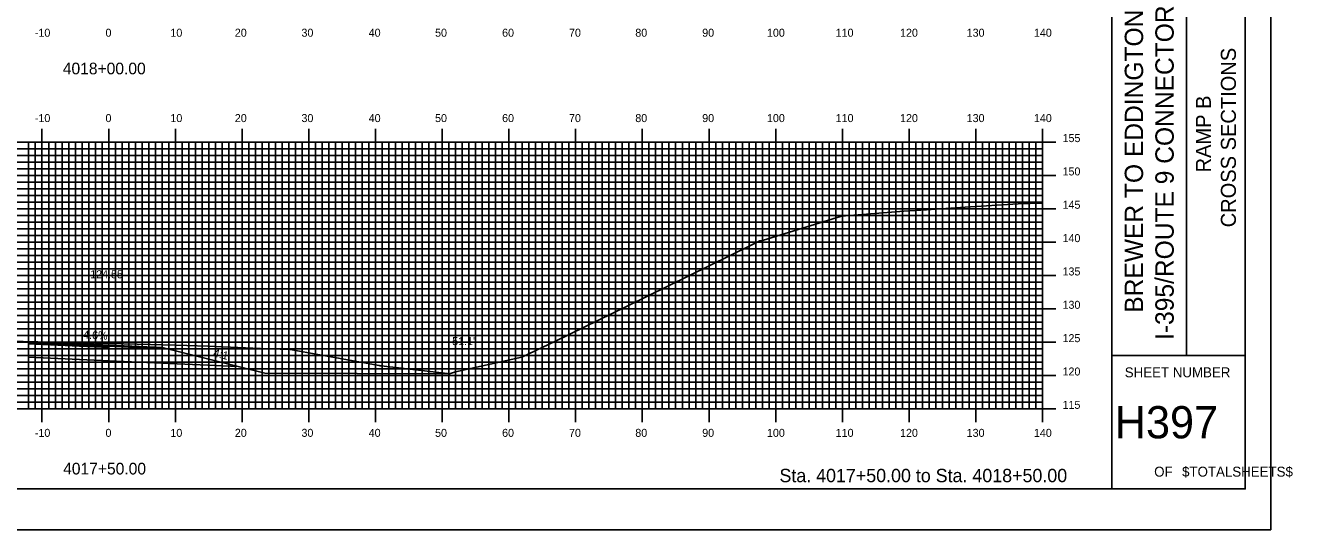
# Model space of a CAD drawing. Extents: x 854508 to 854851, y 364661 to 364881.
# Drawn here: x 854661.3 to 854851.3, y 364661.3 to 364736.9 of the extents above; entities that cross this region are included whole.
import ezdxf

# ---------------------------------------------------------------- set-up
doc = ezdxf.new("R2010")
doc.units = 0
for name, color, linetype in [('ANNOTATION', 7, 'Continuous'), ('BORDER', 7, 'Continuous'), ('D_Roadway_Centerline_Text', 7, 'Continuous'), ('D_Roadway_Edge_Shoulder', 7, 'Continuous'), ('D_Roadway_Edge_TW', 7, 'Continuous'), ('D_Roadway_Pavement', 7, 'Continuous'), ('D_Roadway_SubGrade', 7, 'Continuous'), ('D_Text_Standard', 7, 'Continuous'), ('H_V ANNOTATION', 7, 'Continuous'), ('M_Roadway_Centerline', 7, 'Continuous'), ('MAJOR', 7, 'Continuous'), ('MINOR', 7, 'Continuous'), ('PLOT BOUNDARY', 7, 'Continuous'), ('S_Roadway_Centerline', 7, 'Continuous')]:
    doc.layers.add(name, color=color, linetype=linetype)

msp = doc.modelspace()

# ---------------------------------------------------------------- linework, layer by layer
at = {"layer": 'ANNOTATION'}
msp.add_lwpolyline([(854693.24, 364685.7), (854697.24, 364684.7), (854724.92, 364684.64)], dxfattribs=at)
at = {"layer": 'BORDER'}
for p, q in [((854824.23, 364667.37), (854824.23, 364877.37)), ((854835.42, 364687.38), (854835.42, 364757.38)), ((854824.23, 364687.38), (854844.23, 364687.38))]:
    msp.add_line(p, q, dxfattribs=at)
msp.add_lwpolyline([(854524.23, 364667.37), (854844.23, 364667.37), (854844.23, 364877.37), (854524.23, 364877.37)], close=True, dxfattribs=at)
at = {"layer": 'D_Roadway_Edge_Shoulder'}
msp.add_lwpolyline([(854673.83, 364688.92), (854681.83, 364688.55), (854681.83, 364688.38), (854673.83, 364688.75)], close=True, dxfattribs=at)
at = {"layer": 'D_Roadway_Edge_TW'}
msp.add_lwpolyline([(854661.83, 364689.47), (854673.83, 364688.92), (854673.83, 364688.75), (854661.83, 364689.3)], close=True, dxfattribs=at)
at = {"layer": 'D_Roadway_Pavement'}
msp.add_lwpolyline([(854661.83, 364689.3), (854673.83, 364688.75), (854673.83, 364688.58), (854661.83, 364689.13)], close=True, dxfattribs=at)
for points in [[(854661.83, 364689.3), (854661.83, 364689.13)], [(854673.83, 364688.75), (854673.83, 364688.58)], [(854673.83, 364688.75), (854673.83, 364688.58)]]:
    msp.add_lwpolyline(points, dxfattribs=at)
at = {"layer": 'D_Roadway_SubGrade'}
msp.add_line((854661.83, 364694.43), (854661.83, 364687.13), dxfattribs=at)
for points in [[(854661.83, 364689.13), (854673.83, 364688.58), (854673.83, 364686.58), (854661.83, 364687.13)], [(854673.83, 364688.58), (854673.83, 364688.75), (854681.83, 364688.38), (854681.83, 364688.55), (854693.24, 364685.7), (854673.83, 364686.58)]]:
    msp.add_lwpolyline(points, close=True, dxfattribs=at)
at = {"layer": 'MAJOR'}
for p, q in [((854663.83, 364721.37), (854663.83, 364719.37)), ((854673.83, 364721.37), (854673.83, 364719.37)), ((854683.83, 364721.37), (854683.83, 364719.37)), ((854693.83, 364721.37), (854693.83, 364719.37)), ((854703.83, 364721.37), (854703.83, 364719.37)), ((854713.83, 364721.37), (854713.83, 364719.37)), ((854723.83, 364721.37), (854723.83, 364719.37)), ((854733.83, 364721.37), (854733.83, 364719.37)), ((854743.83, 364721.37), (854743.83, 364719.37)), ((854753.83, 364721.37), (854753.83, 364719.37)), ((854763.83, 364721.37), (854763.83, 364719.37)), ((854773.83, 364721.37), (854773.83, 364719.37)), ((854783.83, 364721.37), (854783.83, 364719.37)), ((854793.83, 364721.37), (854793.83, 364719.37)), ((854803.83, 364721.37), (854803.83, 364719.37)), ((854813.83, 364721.37), (854813.83, 364719.37)), ((854533.83, 364719.37), (854813.83, 364719.37)), ((854533.83, 364719.37), (854813.83, 364719.37)), ((854663.83, 364679.37), (854663.83, 364719.37)), ((854673.83, 364679.37), (854673.83, 364719.37)), ((854683.83, 364679.37), (854683.83, 364719.37)), ((854693.83, 364679.37), (854693.83, 364719.37)), ((854703.83, 364679.37), (854703.83, 364719.37)), ((854713.83, 364679.37), (854713.83, 364719.37)), ((854723.83, 364679.37), (854723.83, 364719.37)), ((854733.83, 364679.37), (854733.83, 364719.37)), ((854743.83, 364679.37), (854743.83, 364719.37)), ((854753.83, 364679.37), (854753.83, 364719.37)), ((854763.83, 364679.37), (854763.83, 364719.37)), ((854773.83, 364679.37), (854773.83, 364719.37)), ((854783.83, 364679.37), (854783.83, 364719.37)), ((854793.83, 364679.37), (854793.83, 364719.37)), ((854803.83, 364679.37), (854803.83, 364719.37)), ((854815.84, 364719.37), (854811.83, 364719.37)), ((854813.83, 364679.37), (854813.83, 364719.37)), ((854813.83, 364679.37), (854813.83, 364719.37)), ((854533.83, 364714.37), (854813.83, 364714.37)), ((854815.84, 364714.37), (854811.83, 364714.37)), ((854533.83, 364709.37), (854813.83, 364709.37)), ((854815.84, 364709.37), (854811.83, 364709.37)), ((854533.83, 364704.37), (854813.83, 364704.37)), ((854815.84, 364704.37), (854811.83, 364704.37)), ((854533.83, 364699.37), (854813.83, 364699.37)), ((854815.84, 364699.37), (854811.83, 364699.37)), ((854533.83, 364694.37), (854813.83, 364694.37)), ((854815.84, 364694.37), (854811.83, 364694.37)), ((854533.83, 364689.37), (854813.83, 364689.37)), ((854815.84, 364689.37), (854811.83, 364689.37)), ((854533.83, 364684.37), (854813.83, 364684.37)), ((854815.84, 364684.37), (854811.83, 364684.37)), ((854533.83, 364679.37), (854813.83, 364679.37)), ((854533.83, 364679.37), (854813.83, 364679.37)), ((854663.83, 364677.37), (854663.83, 364679.37)), ((854673.83, 364677.37), (854673.83, 364679.37)), ((854683.83, 364677.37), (854683.83, 364679.37)), ((854693.83, 364677.37), (854693.83, 364679.37)), ((854703.83, 364677.37), (854703.83, 364679.37)), ((854713.83, 364677.37), (854713.83, 364679.37)), ((854723.83, 364677.37), (854723.83, 364679.37)), ((854733.83, 364677.37), (854733.83, 364679.37)), ((854743.83, 364677.37), (854743.83, 364679.37)), ((854753.83, 364677.37), (854753.83, 364679.37)), ((854763.83, 364677.37), (854763.83, 364679.37)), ((854773.83, 364677.37), (854773.83, 364679.37)), ((854783.83, 364677.37), (854783.83, 364679.37)), ((854793.83, 364677.37), (854793.83, 364679.37)), ((854803.83, 364677.37), (854803.83, 364679.37)), ((854815.84, 364679.37), (854811.83, 364679.37)), ((854813.83, 364677.37), (854813.83, 364679.37))]:
    msp.add_line(p, q, dxfattribs=at)
at = {"layer": 'MINOR'}
for p, q in [((854661.83, 364679.37), (854661.83, 364719.37)), ((854662.83, 364679.37), (854662.83, 364719.37)), ((854664.83, 364679.37), (854664.83, 364719.37)), ((854665.83, 364679.37), (854665.83, 364719.37)), ((854666.83, 364679.37), (854666.83, 364719.37)), ((854667.83, 364679.37), (854667.83, 364719.37)), ((854668.83, 364679.37), (854668.83, 364719.37)), ((854669.83, 364679.37), (854669.83, 364719.37)), ((854670.83, 364679.37), (854670.83, 364719.37)), ((854671.83, 364679.37), (854671.83, 364719.37)), ((854672.83, 364679.37), (854672.83, 364719.37)), ((854674.83, 364679.37), (854674.83, 364719.37)), ((854675.83, 364679.37), (854675.83, 364719.37)), ((854676.83, 364679.37), (854676.83, 364719.37)), ((854677.83, 364679.37), (854677.83, 364719.37)), ((854678.83, 364679.37), (854678.83, 364719.37)), ((854679.83, 364679.37), (854679.83, 364719.37)), ((854680.83, 364679.37), (854680.83, 364719.37)), ((854681.83, 364679.37), (854681.83, 364719.37)), ((854682.83, 364679.37), (854682.83, 364719.37)), ((854684.83, 364679.37), (854684.83, 364719.37)), ((854685.83, 364679.37), (854685.83, 364719.37)), ((854686.83, 364679.37), (854686.83, 364719.37)), ((854687.83, 364679.37), (854687.83, 364719.37)), ((854688.83, 364679.37), (854688.83, 364719.37)), ((854689.83, 364679.37), (854689.83, 364719.37)), ((854690.83, 364679.37), (854690.83, 364719.37)), ((854691.83, 364679.37), (854691.83, 364719.37)), ((854692.83, 364679.37), (854692.83, 364719.37)), ((854694.83, 364679.37), (854694.83, 364719.37)), ((854695.83, 364679.37), (854695.83, 364719.37)), ((854696.83, 364679.37), (854696.83, 364719.37)), ((854697.83, 364679.37), (854697.83, 364719.37)), ((854698.83, 364679.37), (854698.83, 364719.37)), ((854699.83, 364679.37), (854699.83, 364719.37)), ((854700.83, 364679.37), (854700.83, 364719.37)), ((854701.83, 364679.37), (854701.83, 364719.37)), ((854702.83, 364679.37), (854702.83, 364719.37)), ((854704.83, 364679.37), (854704.83, 364719.37)), ((854705.83, 364679.37), (854705.83, 364719.37)), ((854706.83, 364679.37), (854706.83, 364719.37)), ((854707.83, 364679.37), (854707.83, 364719.37)), ((854708.83, 364679.37), (854708.83, 364719.37)), ((854709.83, 364679.37), (854709.83, 364719.37)), ((854710.83, 364679.37), (854710.83, 364719.37)), ((854711.83, 364679.37), (854711.83, 364719.37)), ((854712.83, 364679.37), (854712.83, 364719.37)), ((854714.83, 364679.37), (854714.83, 364719.37)), ((854715.83, 364679.37), (854715.83, 364719.37)), ((854716.83, 364679.37), (854716.83, 364719.37)), ((854717.83, 364679.37), (854717.83, 364719.37)), ((854718.83, 364679.37), (854718.83, 364719.37)), ((854719.83, 364679.37), (854719.83, 364719.37)), ((854720.83, 364679.37), (854720.83, 364719.37)), ((854721.83, 364679.37), (854721.83, 364719.37)), ((854722.83, 364679.37), (854722.83, 364719.37)), ((854724.83, 364679.37), (854724.83, 364719.37)), ((854725.83, 364679.37), (854725.83, 364719.37)), ((854726.83, 364679.37), (854726.83, 364719.37)), ((854727.83, 364679.37), (854727.83, 364719.37)), ((854728.83, 364679.37), (854728.83, 364719.37)), ((854729.83, 364679.37), (854729.83, 364719.37)), ((854730.83, 364679.37), (854730.83, 364719.37)), ((854731.83, 364679.37), (854731.83, 364719.37)), ((854732.83, 364679.37), (854732.83, 364719.37)), ((854734.83, 364679.37), (854734.83, 364719.37)), ((854735.83, 364679.37), (854735.83, 364719.37)), ((854736.83, 364679.37), (854736.83, 364719.37)), ((854737.83, 364679.37), (854737.83, 364719.37)), ((854738.83, 364679.37), (854738.83, 364719.37)), ((854739.83, 364679.37), (854739.83, 364719.37)), ((854740.83, 364679.37), (854740.83, 364719.37)), ((854741.83, 364679.37), (854741.83, 364719.37)), ((854742.83, 364679.37), (854742.83, 364719.37)), ((854744.83, 364679.37), (854744.83, 364719.37)), ((854745.83, 364679.37), (854745.83, 364719.37)), ((854746.83, 364679.37), (854746.83, 364719.37)), ((854747.83, 364679.37), (854747.83, 364719.37)), ((854748.83, 364679.37), (854748.83, 364719.37)), ((854749.83, 364679.37), (854749.83, 364719.37)), ((854750.83, 364679.37), (854750.83, 364719.37)), ((854751.83, 364679.37), (854751.83, 364719.37)), ((854752.83, 364679.37), (854752.83, 364719.37)), ((854754.83, 364679.37), (854754.83, 364719.37)), ((854755.83, 364679.37), (854755.83, 364719.37)), ((854756.83, 364679.37), (854756.83, 364719.37)), ((854757.83, 364679.37), (854757.83, 364719.37)), ((854758.83, 364679.37), (854758.83, 364719.37)), ((854759.83, 364679.37), (854759.83, 364719.37)), ((854760.83, 364679.37), (854760.83, 364719.37)), ((854761.83, 364679.37), (854761.83, 364719.37)), ((854762.83, 364679.37), (854762.83, 364719.37)), ((854764.83, 364679.37), (854764.83, 364719.37)), ((854765.83, 364679.37), (854765.83, 364719.37)), ((854766.83, 364679.37), (854766.83, 364719.37)), ((854767.83, 364679.37), (854767.83, 364719.37)), ((854768.83, 364679.37), (854768.83, 364719.37)), ((854769.83, 364679.37), (854769.83, 364719.37)), ((854770.83, 364679.37), (854770.83, 364719.37)), ((854771.83, 364679.37), (854771.83, 364719.37)), ((854772.83, 364679.37), (854772.83, 364719.37)), ((854774.83, 364679.37), (854774.83, 364719.37)), ((854775.83, 364679.37), (854775.83, 364719.37)), ((854776.83, 364679.37), (854776.83, 364719.37)), ((854777.83, 364679.37), (854777.83, 364719.37)), ((854778.83, 364679.37), (854778.83, 364719.37)), ((854779.83, 364679.37), (854779.83, 364719.37)), ((854780.83, 364679.37), (854780.83, 364719.37)), ((854781.83, 364679.37), (854781.83, 364719.37)), ((854782.83, 364679.37), (854782.83, 364719.37)), ((854784.83, 364679.37), (854784.83, 364719.37)), ((854785.83, 364679.37), (854785.83, 364719.37)), ((854786.83, 364679.37), (854786.83, 364719.37)), ((854787.83, 364679.37), (854787.83, 364719.37)), ((854788.83, 364679.37), (854788.83, 364719.37)), ((854789.83, 364679.37), (854789.83, 364719.37)), ((854790.83, 364679.37), (854790.83, 364719.37)), ((854791.83, 364679.37), (854791.83, 364719.37)), ((854792.83, 364679.37), (854792.83, 364719.37)), ((854794.83, 364679.37), (854794.83, 364719.37)), ((854795.83, 364679.37), (854795.83, 364719.37)), ((854796.83, 364679.37), (854796.83, 364719.37)), ((854797.83, 364679.37), (854797.83, 364719.37)), ((854798.83, 364679.37), (854798.83, 364719.37)), ((854799.83, 364679.37), (854799.83, 364719.37)), ((854800.83, 364679.37), (854800.83, 364719.37)), ((854801.83, 364679.37), (854801.83, 364719.37)), ((854802.83, 364679.37), (854802.83, 364719.37)), ((854804.83, 364679.37), (854804.83, 364719.37)), ((854805.83, 364679.37), (854805.83, 364719.37)), ((854806.83, 364679.37), (854806.83, 364719.37)), ((854807.83, 364679.37), (854807.83, 364719.37)), ((854808.83, 364679.37), (854808.83, 364719.37)), ((854809.83, 364679.37), (854809.83, 364719.37)), ((854810.83, 364679.37), (854810.83, 364719.37)), ((854811.83, 364679.37), (854811.83, 364719.37)), ((854812.83, 364679.37), (854812.83, 364719.37)), ((854533.83, 364718.37), (854813.83, 364718.37)), ((854533.83, 364717.37), (854813.83, 364717.37)), ((854813.83, 364718.37), (854811.83, 364718.37)), ((854813.83, 364717.37), (854811.83, 364717.37)), ((854533.83, 364716.37), (854813.83, 364716.37)), ((854533.83, 364715.37), (854813.83, 364715.37)), ((854813.83, 364716.37), (854811.83, 364716.37)), ((854813.83, 364715.37), (854811.83, 364715.37)), ((854533.83, 364713.37), (854813.83, 364713.37)), ((854813.83, 364713.37), (854811.83, 364713.37)), ((854533.83, 364712.37), (854813.83, 364712.37)), ((854533.83, 364711.37), (854813.83, 364711.37)), ((854813.83, 364712.37), (854811.83, 364712.37)), ((854813.83, 364711.37), (854811.83, 364711.37)), ((854533.83, 364710.37), (854813.83, 364710.37)), ((854813.83, 364710.37), (854811.83, 364710.37)), ((854533.83, 364708.37), (854813.83, 364708.37)), ((854533.83, 364707.37), (854813.83, 364707.37)), ((854813.83, 364708.37), (854811.83, 364708.37)), ((854813.83, 364707.37), (854811.83, 364707.37)), ((854533.83, 364706.37), (854813.83, 364706.37)), ((854533.83, 364705.37), (854813.83, 364705.37)), ((854813.83, 364706.37), (854811.83, 364706.37)), ((854813.83, 364705.37), (854811.83, 364705.37)), ((854533.83, 364703.37), (854813.83, 364703.37)), ((854533.83, 364702.37), (854813.83, 364702.37)), ((854813.83, 364703.37), (854811.83, 364703.37)), ((854813.83, 364702.37), (854811.83, 364702.37)), ((854533.83, 364701.37), (854813.83, 364701.37)), ((854533.83, 364700.37), (854813.83, 364700.37)), ((854813.83, 364701.37), (854811.83, 364701.37)), ((854813.83, 364700.37), (854811.83, 364700.37)), ((854533.83, 364698.37), (854813.83, 364698.37)), ((854813.83, 364698.37), (854811.83, 364698.37)), ((854533.83, 364697.37), (854813.83, 364697.37)), ((854533.83, 364696.37), (854813.83, 364696.37)), ((854813.83, 364697.37), (854811.83, 364697.37)), ((854813.83, 364696.37), (854811.83, 364696.37)), ((854533.83, 364695.37), (854813.83, 364695.37)), ((854813.83, 364695.37), (854811.83, 364695.37)), ((854533.83, 364693.37), (854813.83, 364693.37)), ((854533.83, 364692.37), (854813.83, 364692.37)), ((854813.83, 364693.37), (854811.83, 364693.37)), ((854813.83, 364692.37), (854811.83, 364692.37)), ((854533.83, 364691.37), (854813.83, 364691.37)), ((854533.83, 364690.37), (854813.83, 364690.37)), ((854813.83, 364691.37), (854811.83, 364691.37)), ((854813.83, 364690.37), (854811.83, 364690.37)), ((854533.83, 364688.37), (854813.83, 364688.37)), ((854813.83, 364688.37), (854811.83, 364688.37)), ((854533.83, 364687.37), (854813.83, 364687.37)), ((854533.83, 364686.37), (854813.83, 364686.37)), ((854813.83, 364687.37), (854811.83, 364687.37)), ((854813.83, 364686.37), (854811.83, 364686.37)), ((854533.83, 364685.37), (854813.83, 364685.37)), ((854813.83, 364685.37), (854811.83, 364685.37)), ((854533.83, 364683.37), (854813.83, 364683.37)), ((854813.83, 364683.37), (854811.83, 364683.37)), ((854533.83, 364682.37), (854813.83, 364682.37)), ((854533.83, 364681.37), (854813.83, 364681.37)), ((854813.83, 364682.37), (854811.83, 364682.37)), ((854813.83, 364681.37), (854811.83, 364681.37)), ((854533.83, 364680.37), (854813.83, 364680.37)), ((854813.83, 364680.37), (854811.83, 364680.37))]:
    msp.add_line(p, q, dxfattribs=at)
at = {"layer": 'PLOT BOUNDARY'}
msp.add_lwpolyline([(854508.05, 364661.25), (854848.05, 364661.25), (854848.05, 364881.25), (854508.05, 364881.25)], close=True, dxfattribs=at)
at = {"layer": 'S_Roadway_Centerline'}
msp.add_lwpolyline([(854654.45, 364689.62), (854674.07, 364689.18), (854680.12, 364689.03), (854685.56, 364688.87), (854688.71, 364688.76), (854696.59, 364688.44), (854701.02, 364688.25), (854714.4, 364685.85), (854714.52, 364685.83), (854714.67, 364685.8), (854724.62, 364684.66), (854724.92, 364684.64), (854725.83, 364684.93), (854735.76, 364687.1), (854740.83, 364689.53), (854751.58, 364694.79), (854770.04, 364703.85), (854771.45, 364704.54), (854771.84, 364704.63), (854783.67, 364708.24), (854793.05, 364709.01), (854796.43, 364709.22), (854802.22, 364709.63), (854810.16, 364710.11), (854813.83, 364710.23)], dxfattribs=at)

# ---------------------------------------------------------------- texts
at = {"layer": 'ANNOTATION'}
for s, rotation, p in [('4.6%', 357.3663, (854669.98, 364689.9)), ('4:1', 345.9638, (854689.43, 364687.24))]:
    msp.add_text(s, height=1.2, rotation=rotation, dxfattribs=at).set_placement(p)
at = {"layer": 'BORDER'}
for s, height, p in [('I-395/ROUTE 9 CONNECTOR', 2.7557, (854833.5, 364689.7)), ('BREWER TO EDDINGTON', 2.7557, (854828.91, 364693.78)), ('CROSS SECTIONS', 2.25, (854842.82, 364706.59)), ('RAMP B', 2.25, (854839.07, 364714.82))]:
    msp.add_text(s, height=height, rotation=90, dxfattribs=at).set_placement(p)
for s, height, p in [('SHEET NUMBER', 1.4905, (854826.16, 364684.1)), ('H397', 4.839, (854824.67, 364674.94)), ('OF', 1.491, (854830.57, 364669.2)), ('$TOTALSHEETS$', 1.4905, (854834.75, 364669.2))]:
    msp.add_text(s, height=height, dxfattribs=at).set_placement(p)
at = {"layer": 'D_Roadway_Centerline_Text'}
msp.add_text('124.55', height=1.2, dxfattribs=at).set_placement((854671.06, 364698.95))
at = {"layer": 'D_Text_Standard'}
msp.add_text("51.1'", height=1.2, dxfattribs=at).set_placement((854725.32, 364688.92))
at = {"layer": 'H_V ANNOTATION'}
for s, height, p in [('-10', 1.2, (854662.76, 364735.17)), ('0', 1.2, (854673.35, 364735.17)), ('10', 1.2, (854683.08, 364735.17)), ('20', 1.2, (854692.74, 364735.17)), ('30', 1.2, (854702.73, 364735.17)), ('40', 1.2, (854712.81, 364735.17)), ('50', 1.2, (854722.76, 364735.17)), ('60', 1.2, (854732.81, 364735.17)), ('70', 1.2, (854742.84, 364735.17)), ('80', 1.2, (854752.78, 364735.17)), ('90', 1.2, (854762.81, 364735.17)), ('100', 1.2, (854772.52, 364735.17)), ('110', 1.2, (854782.82, 364735.17)), ('120', 1.2, (854792.47, 364735.17)), ('130', 1.2, (854802.46, 364735.17)), ('140', 1.2, (854812.54, 364735.17)), ('4018+00.00', 1.75, (854666.95, 364729.53)), ('-10', 1.2, (854662.76, 364722.37)), ('0', 1.2, (854673.35, 364722.37)), ('10', 1.2, (854683.08, 364722.37)), ('20', 1.2, (854692.74, 364722.37)), ('30', 1.2, (854702.73, 364722.37)), ('40', 1.2, (854712.81, 364722.37)), ('50', 1.2, (854722.76, 364722.37)), ('60', 1.2, (854732.81, 364722.37)), ('70', 1.2, (854742.84, 364722.37)), ('80', 1.2, (854752.78, 364722.37)), ('90', 1.2, (854762.81, 364722.37)), ('100', 1.2, (854772.52, 364722.37)), ('110', 1.2, (854782.82, 364722.37)), ('120', 1.2, (854792.47, 364722.37)), ('130', 1.2, (854802.46, 364722.37)), ('140', 1.2, (854812.54, 364722.37)), ('155', 1.2, (854816.83, 364719.37)), ('150', 1.2, (854816.83, 364714.37)), ('145', 1.2, (854816.83, 364709.37)), ('140', 1.2, (854816.83, 364704.37)), ('135', 1.2, (854816.83, 364699.37)), ('130', 1.2, (854816.83, 364694.37)), ('125', 1.2, (854816.83, 364689.37)), ('120', 1.2, (854816.83, 364684.37)), ('115', 1.2, (854816.83, 364679.37)), ('-10', 1.2, (854662.76, 364675.17)), ('0', 1.2, (854673.35, 364675.17)), ('10', 1.2, (854683.08, 364675.17)), ('20', 1.2, (854692.74, 364675.17)), ('30', 1.2, (854702.73, 364675.17)), ('40', 1.2, (854712.81, 364675.17)), ('50', 1.2, (854722.76, 364675.17)), ('60', 1.2, (854732.81, 364675.17)), ('70', 1.2, (854742.84, 364675.17)), ('80', 1.2, (854752.78, 364675.17)), ('90', 1.2, (854762.81, 364675.17)), ('100', 1.2, (854772.52, 364675.17)), ('110', 1.2, (854782.82, 364675.17)), ('120', 1.2, (854792.47, 364675.17)), ('130', 1.2, (854802.46, 364675.17)), ('140', 1.2, (854812.54, 364675.17)), ('4017+50.00', 1.75, (854667, 364669.53)), ('Sta. 4017+50.00 to Sta. 4018+50.00', 2.0004, (854774.39, 364668.37))]:
    msp.add_text(s, height=height, dxfattribs=at).set_placement(p)
at = {"layer": 'M_Roadway_Centerline'}
for s, p in [('C', (854685.55, 364688.87)), ('L', (854685.56, 364688.87))]:
    msp.add_text(s, height=0.0146, dxfattribs=at).set_placement(p)

doc.saveas('drawing.dxf')
